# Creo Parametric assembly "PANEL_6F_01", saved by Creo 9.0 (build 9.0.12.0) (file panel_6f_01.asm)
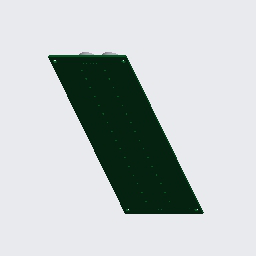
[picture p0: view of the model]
Units: millimeter Newton Second (mmNs); MM, TONNE, SECS

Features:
  1. coordinate system "PANEL_6F_01"
  2. imported feature "Import Feature id 4"
  3. component "PCB_6F"
  4. component "TX_6F_T1"
  5. component "TX_6F_T1"
  6. component "TX_6F_T1"
  7. component "TX_6F_T1"
  8. component "TX_6F_T1"
  9. component "TX_6F_T1"
  10. component "TX_6F_T1"
  11. component "TX_6F_T1"
  12. component "TX_6F_T1"
  13. component "TX_6F_T1"
  14. component "TX_6F_T1"
  15. component "TX_6F_T1"
  16. component "TX_6F_T1"
  17. component "TX_6F_T1"
  18. component "TX_6F_T1"
  19. component "TX_6F_T1"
